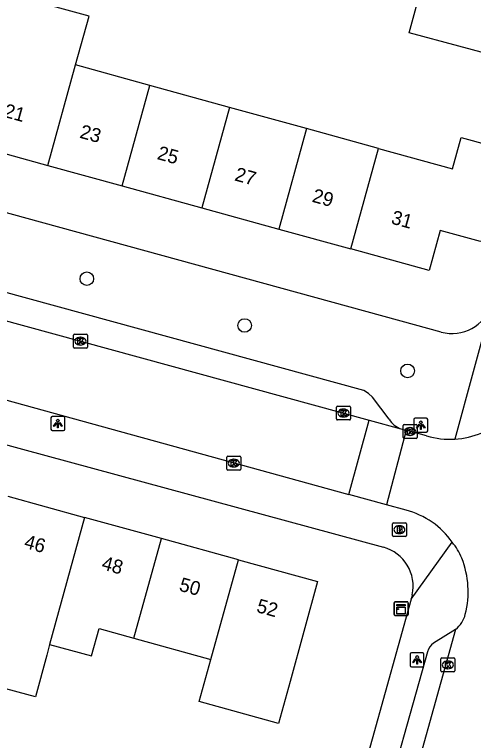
# Model space of a CAD drawing. Extents: x 159822 to 160765, y 380693 to 381634.
# Drawn here: x 160334.7 to 160367.7, y 380978.1 to 381030.3 of the extents above; entities that cross this region are included whole.
import ezdxf

# ---------------------------------------------------------------- set-up
doc = ezdxf.new("R2010")
doc.units = 0
for name, color, linetype in [('IMGEO_Boom', 7, 'Continuous'), ('IMGEO_Brandkraan', 7, 'Continuous'), ('IMGEO_Kast', 7, 'Continuous'), ('IMGEO_Kolk', 7, 'Continuous'), ('IMGEO_Lichtpunt', 7, 'Continuous'), ('IMGEO_Pand', 7, 'Continuous'), ('IMGEO_Pand_nummerreeks', 7, 'Continuous'), ('IMGEO_Rijbaan_lokaal_open', 7, 'Continuous'), ('IMGEO_Voetpad_open', 7, 'Continuous')]:
    doc.layers.add(name, color=color, linetype=linetype)

msp = doc.modelspace()

# ---------------------------------------------------------------- linework, layer by layer
at = {"layer": 'IMGEO_Boom'}
for centre in [(160339.893, 381011.267), (160351.236, 381007.905), (160362.95, 381004.636)]:
    msp.add_circle(centre, 0.489, dxfattribs=at)
at = {"layer": 'IMGEO_Brandkraan'}
for p, q in [((160361.861, 380992.794), (160361.861, 380993.646)), ((160361.936, 380993.72), (160362.788, 380993.72)), ((160362.349, 380993.5), (160362.374, 380993.5)), ((160362.862, 380993.646), (160362.862, 380992.794)), ((160362.372, 380992.94), (160362.347, 380992.94)), ((160362.788, 380992.72), (160361.936, 380992.72))]:
    msp.add_line(p, q, dxfattribs=at)
for points in [[(160361.861, 380992.794), (160361.861, 380993.646)], [(160361.936, 380993.72), (160362.788, 380993.72)], [(160362.862, 380993.646), (160362.862, 380992.794)], [(160362.209, 380993.42), (160362.209, 380993.02), (160362.422, 380993.02)], [(160362.44, 380993.42), (160362.209, 380993.42)], [(160362.388, 380993.339), (160362.334, 380993.339), (160362.334, 380993.263)], [(160362.334, 380993.263), (160362.387, 380993.263)], [(160362.396, 380993.187), (160362.334, 380993.187), (160362.334, 380993.106)], [(160362.334, 380993.106), (160362.396, 380993.106)], [(160362.788, 380992.72), (160361.936, 380992.72)]]:
    msp.add_lwpolyline(points, dxfattribs=at)
for centre, radius, start, end in [((160361.938, 380993.644), 0.0765, 91.552, 178.448), ((160361.938, 380993.644), 0.0765, 91.552, 178.448), ((160362.786, 380993.644), 0.0765, 1.552, 88.448), ((160362.786, 380993.644), 0.0765, 1.552, 88.448), ((160362.389, 380993.301), 0.0379, 267.8285, 90.9355), ((160362.397, 380993.146), 0.0404, 269.8759, 90.5077), ((160362.428, 380993.271), 0.251, 268.6676, 293.5347), ((160362.444, 380993.275), 0.145, 59.4692, 91.5367), ((160362.469, 380993.322), 0.0922, 285.5137, 58.1501), ((160362.474, 380993.13), 0.105, 301.3115, 78.989), ((160361.938, 380992.796), 0.0765, 181.552, 268.448), ((160361.938, 380992.796), 0.0765, 181.552, 268.448), ((160362.786, 380992.796), 0.0765, 271.552, 358.448), ((160362.786, 380992.796), 0.0765, 271.552, 358.448)]:
    msp.add_arc(centre, radius, start, end, dxfattribs=at)
for centre, major_axis, ratio, start_param, end_param in [((160362.348, 380993.22), (-0.387, 0.002), 0.722429, 4.712389, 7.853982), ((160362.373, 380993.22), (-0.39, 0.002), 0.717154, 1.570796, 4.712389)]:
    msp.add_ellipse(centre, major_axis=major_axis, ratio=ratio, start_param=start_param, end_param=end_param, dxfattribs=at)
at = {"layer": 'IMGEO_Kast'}
for p, q in [((160361.985, 380987.116), (160361.985, 380987.957)), ((160361.985, 380987.957), (160361.985, 380987.116)), ((160362.06, 380988.041), (160362.901, 380988.041)), ((160362.901, 380988.041), (160362.06, 380988.041)), ((160362.985, 380987.966), (160362.985, 380987.125)), ((160362.985, 380987.125), (160362.985, 380987.966)), ((160362.91, 380987.041), (160362.069, 380987.041)), ((160362.069, 380987.041), (160362.91, 380987.041))]:
    msp.add_line(p, q, dxfattribs=at)
for points in [[(160362.18, 380987.831), (160362.78, 380987.831), (160362.78, 380987.746), (160362.18, 380987.746), (160362.18, 380987.831)], [(160362.18, 380987.656), (160362.78, 380987.656), (160362.78, 380987.167), (160362.18, 380987.167), (160362.18, 380987.656)]]:
    msp.add_lwpolyline(points, dxfattribs=at)
msp.add_circle((160362.264, 380987.505), 0.0377, dxfattribs=at)
for centre, start, end in [((160362.063, 380987.963), 92.4484, 184.2845), ((160362.063, 380987.963), 92.4484, 184.2845), ((160362.907, 380987.963), 2.4484, 94.2845), ((160362.907, 380987.963), 2.4484, 94.2845), ((160362.063, 380987.119), 182.4484, 274.2845), ((160362.063, 380987.119), 182.4484, 274.2845), ((160362.907, 380987.119), 272.4484, 4.2845), ((160362.907, 380987.119), 272.4484, 4.2845)]:
    msp.add_arc(centre, 0.0779, start, end, dxfattribs=at)
at = {"layer": 'IMGEO_Kolk'}
for p, q in [((160338.931, 381006.354), (160338.931, 381007.206)), ((160339.006, 381007.28), (160339.858, 381007.28)), ((160339.419, 381007.06), (160339.444, 381007.06)), ((160339.932, 381007.206), (160339.932, 381006.354)), ((160339.858, 381006.28), (160339.006, 381006.28)), ((160339.442, 381006.5), (160339.417, 381006.5)), ((160357.844, 381001.181), (160357.844, 381002.033)), ((160357.919, 381002.107), (160358.771, 381002.107)), ((160358.332, 381001.887), (160358.357, 381001.887)), ((160358.845, 381002.033), (160358.845, 381001.181)), ((160358.355, 381001.327), (160358.33, 381001.327)), ((160358.771, 381001.107), (160357.919, 381001.107)), ((160362.704, 381000.782), (160363.556, 381000.782)), ((160362.629, 380999.856), (160362.629, 381000.708)), ((160363.117, 381000.562), (160363.142, 381000.562)), ((160363.63, 381000.708), (160363.63, 380999.856)), ((160363.556, 380999.782), (160362.704, 380999.782)), ((160363.14, 381000.002), (160363.115, 381000.002)), ((160349.955, 380997.581), (160349.955, 380998.433)), ((160350.03, 380998.507), (160350.882, 380998.507)), ((160350.443, 380998.287), (160350.468, 380998.287)), ((160350.956, 380998.433), (160350.956, 380997.581)), ((160350.466, 380997.727), (160350.441, 380997.727)), ((160350.882, 380997.507), (160350.03, 380997.507)), ((160365.343, 380983.068), (160365.343, 380983.92)), ((160365.418, 380983.994), (160366.27, 380983.994)), ((160365.831, 380983.774), (160365.856, 380983.774)), ((160366.344, 380983.92), (160366.344, 380983.068)), ((160365.854, 380983.214), (160365.829, 380983.214)), ((160366.27, 380982.994), (160365.418, 380982.994))]:
    msp.add_line(p, q, dxfattribs=at)
for points in [[(160338.931, 381006.354), (160338.931, 381007.206)], [(160339.006, 381007.28), (160339.858, 381007.28)], [(160339.932, 381007.206), (160339.932, 381006.354)], [(160339.252, 381006.98), (160339.375, 381006.98), (160339.375, 381006.829), (160339.505, 381006.98), (160339.669, 381006.98), (160339.523, 381006.829), (160339.676, 381006.58), (160339.524, 381006.58), (160339.439, 381006.744), (160339.375, 381006.677), (160339.375, 381006.58), (160339.252, 381006.58), (160339.252, 381006.98)], [(160339.858, 381006.28), (160339.006, 381006.28)], [(160357.844, 381001.181), (160357.844, 381002.033)], [(160357.919, 381002.107), (160358.771, 381002.107)], [(160358.845, 381002.033), (160358.845, 381001.181)], [(160358.165, 381001.807), (160358.288, 381001.807), (160358.288, 381001.656), (160358.418, 381001.807), (160358.582, 381001.807), (160358.436, 381001.656), (160358.589, 381001.407), (160358.437, 381001.407), (160358.352, 381001.571), (160358.288, 381001.504), (160358.288, 381001.407), (160358.165, 381001.407), (160358.165, 381001.807)], [(160358.771, 381001.107), (160357.919, 381001.107)], [(160362.704, 381000.782), (160363.556, 381000.782)], [(160362.629, 380999.856), (160362.629, 381000.708)], [(160362.95, 381000.482), (160363.073, 381000.482), (160363.073, 381000.331), (160363.203, 381000.482), (160363.367, 381000.482), (160363.221, 381000.331), (160363.374, 381000.082), (160363.222, 381000.082), (160363.137, 381000.246), (160363.073, 381000.179), (160363.073, 381000.082), (160362.95, 381000.082), (160362.95, 381000.482)], [(160363.63, 381000.708), (160363.63, 380999.856)], [(160363.556, 380999.782), (160362.704, 380999.782)], [(160349.955, 380997.581), (160349.955, 380998.433)], [(160350.03, 380998.507), (160350.882, 380998.507)], [(160350.276, 380998.207), (160350.399, 380998.207), (160350.399, 380998.056), (160350.529, 380998.207), (160350.693, 380998.207), (160350.547, 380998.056), (160350.7, 380997.807), (160350.548, 380997.807), (160350.463, 380997.971), (160350.399, 380997.904), (160350.399, 380997.807), (160350.276, 380997.807), (160350.276, 380998.207)], [(160350.956, 380998.433), (160350.956, 380997.581)], [(160350.882, 380997.507), (160350.03, 380997.507)], [(160365.343, 380983.068), (160365.343, 380983.92)], [(160365.418, 380983.994), (160366.27, 380983.994)], [(160365.664, 380983.694), (160365.787, 380983.694), (160365.787, 380983.543), (160365.917, 380983.694), (160366.081, 380983.694), (160365.935, 380983.543), (160366.088, 380983.294), (160365.936, 380983.294), (160365.851, 380983.458), (160365.787, 380983.391), (160365.787, 380983.294), (160365.664, 380983.294), (160365.664, 380983.694)], [(160366.344, 380983.92), (160366.344, 380983.068)], [(160366.27, 380982.994), (160365.418, 380982.994)]]:
    msp.add_lwpolyline(points, dxfattribs=at)
for centre, start, end in [((160339.008, 381007.204), 91.552, 178.448), ((160339.008, 381007.204), 91.552, 178.448), ((160339.856, 381007.204), 1.552, 88.448), ((160339.856, 381007.204), 1.552, 88.448), ((160339.008, 381006.356), 181.552, 268.448), ((160339.008, 381006.356), 181.552, 268.448), ((160339.856, 381006.356), 271.552, 358.448), ((160339.856, 381006.356), 271.552, 358.448), ((160357.921, 381002.031), 91.552, 178.448), ((160357.921, 381002.031), 91.552, 178.448), ((160358.769, 381002.031), 1.552, 88.448), ((160358.769, 381002.031), 1.552, 88.448), ((160357.921, 381001.183), 181.552, 268.448), ((160357.921, 381001.183), 181.552, 268.448), ((160358.769, 381001.183), 271.552, 358.448), ((160358.769, 381001.183), 271.552, 358.448), ((160362.706, 381000.706), 91.552, 178.448), ((160362.706, 381000.706), 91.552, 178.448), ((160363.554, 381000.706), 1.552, 88.448), ((160363.554, 381000.706), 1.552, 88.448), ((160362.706, 380999.858), 181.552, 268.448), ((160362.706, 380999.858), 181.552, 268.448), ((160363.554, 380999.858), 271.552, 358.448), ((160363.554, 380999.858), 271.552, 358.448), ((160350.032, 380998.431), 91.552, 178.448), ((160350.032, 380998.431), 91.552, 178.448), ((160350.88, 380998.431), 1.552, 88.448), ((160350.88, 380998.431), 1.552, 88.448), ((160350.032, 380997.583), 181.552, 268.448), ((160350.032, 380997.583), 181.552, 268.448), ((160350.88, 380997.583), 271.552, 358.448), ((160350.88, 380997.583), 271.552, 358.448), ((160365.42, 380983.918), 91.552, 178.448), ((160365.42, 380983.918), 91.552, 178.448), ((160366.268, 380983.918), 1.552, 88.448), ((160366.268, 380983.918), 1.552, 88.448), ((160365.42, 380983.07), 181.552, 268.448), ((160365.42, 380983.07), 181.552, 268.448), ((160366.268, 380983.07), 271.552, 358.448), ((160366.268, 380983.07), 271.552, 358.448)]:
    msp.add_arc(centre, 0.0765, start, end, dxfattribs=at)
for centre, major_axis, ratio, start_param, end_param in [((160339.418, 381006.78), (-0.387, 0.002), 0.722429, 4.712389, 7.853982), ((160339.443, 381006.78), (-0.39, 0.002), 0.717154, 1.570796, 4.712389), ((160358.331, 381001.607), (-0.387, 0.002), 0.722429, 4.712389, 7.853982), ((160358.356, 381001.607), (-0.39, 0.002), 0.717154, 1.570796, 4.712389), ((160363.116, 381000.282), (-0.387, 0.002), 0.722429, 4.712389, 7.853982), ((160363.141, 381000.282), (-0.39, 0.002), 0.717154, 1.570796, 4.712389), ((160350.442, 380998.007), (-0.387, 0.002), 0.722429, 4.712389, 7.853982), ((160350.467, 380998.007), (-0.39, 0.002), 0.717154, 1.570796, 4.712389), ((160365.83, 380983.494), (-0.387, 0.002), 0.722429, 4.712389, 7.853982), ((160365.855, 380983.494), (-0.39, 0.002), 0.717154, 1.570796, 4.712389)]:
    msp.add_ellipse(centre, major_axis=major_axis, ratio=ratio, start_param=start_param, end_param=end_param, dxfattribs=at)
at = {"layer": 'IMGEO_Lichtpunt'}
for p, q in [((160338.217, 381001.355), (160337.409, 381001.355)), ((160338.217, 381001.355), (160337.409, 381001.355)), ((160337.315, 381001.26), (160337.315, 381000.453)), ((160337.315, 381001.26), (160337.315, 381000.453)), ((160338.311, 381000.453), (160338.311, 381001.26)), ((160338.311, 381000.453), (160338.311, 381001.26)), ((160363.398, 381001.141), (160363.398, 381000.334)), ((160363.398, 381001.141), (160363.398, 381000.334)), ((160364.3, 381001.236), (160363.492, 381001.236)), ((160364.3, 381001.236), (160363.492, 381001.236)), ((160364.394, 381000.334), (160364.394, 381001.141)), ((160364.394, 381000.334), (160364.394, 381001.141)), ((160337.409, 381000.359), (160338.217, 381000.359)), ((160337.409, 381000.359), (160338.217, 381000.359)), ((160363.492, 381000.24), (160364.3, 381000.24)), ((160363.492, 381000.24), (160364.3, 381000.24)), ((160363.132, 380984.261), (160363.132, 380983.454)), ((160363.132, 380984.261), (160363.132, 380983.454)), ((160364.034, 380984.356), (160363.226, 380984.356)), ((160364.034, 380984.356), (160363.226, 380984.356)), ((160364.128, 380983.454), (160364.128, 380984.261)), ((160364.128, 380983.454), (160364.128, 380984.261)), ((160363.226, 380983.36), (160364.034, 380983.36)), ((160363.226, 380983.36), (160364.034, 380983.36))]:
    msp.add_line(p, q, dxfattribs=at)
for points in [[(160337.689, 381000.924), (160337.728, 381000.896), (160337.54, 381000.634), (160337.502, 381000.661), (160337.689, 381000.924)], [(160337.791, 381000.876), (160337.838, 381000.876), (160337.838, 381000.554), (160337.791, 381000.554), (160337.791, 381000.876)], [(160337.901, 381000.896), (160337.939, 381000.923), (160338.126, 381000.661), (160338.087, 381000.633), (160337.901, 381000.896)], [(160363.772, 381000.805), (160363.811, 381000.777), (160363.623, 381000.515), (160363.585, 381000.542), (160363.772, 381000.805)], [(160363.984, 381000.777), (160364.022, 381000.804), (160364.209, 381000.542), (160364.17, 381000.514), (160363.984, 381000.777)], [(160363.874, 381000.757), (160363.921, 381000.757), (160363.921, 381000.435), (160363.874, 381000.435), (160363.874, 381000.757)], [(160363.506, 380983.925), (160363.545, 380983.897), (160363.357, 380983.635), (160363.319, 380983.662), (160363.506, 380983.925)], [(160363.608, 380983.877), (160363.655, 380983.877), (160363.655, 380983.555), (160363.608, 380983.555), (160363.608, 380983.877)], [(160363.718, 380983.897), (160363.756, 380983.924), (160363.943, 380983.662), (160363.904, 380983.634), (160363.718, 380983.897)]]:
    msp.add_lwpolyline(points, dxfattribs=at)
for centre in [(160337.814, 381001.058), (160363.897, 381000.939), (160363.631, 380984.059)]:
    msp.add_circle(centre, 0.0994, dxfattribs=at)
for centre, start, end in [((160337.409, 381001.26), 90, 180), ((160337.409, 381001.26), 90, 180), ((160338.217, 381001.26), 0, 90), ((160338.217, 381001.26), 0, 90), ((160363.492, 381001.141), 90, 180), ((160363.492, 381001.141), 90, 180), ((160364.3, 381001.141), 0, 90), ((160364.3, 381001.141), 0, 90), ((160337.409, 381000.453), 180, 270), ((160337.409, 381000.453), 180, 270), ((160338.217, 381000.453), 270, 0), ((160338.217, 381000.453), 270, 360), ((160363.492, 381000.334), 180, 270), ((160363.492, 381000.334), 180, 270), ((160364.3, 381000.334), 270, 0), ((160364.3, 381000.334), 270, 360), ((160363.226, 380984.261), 90, 180), ((160363.226, 380984.261), 90, 180), ((160364.034, 380984.261), 0, 90), ((160364.034, 380984.261), 0, 90), ((160363.226, 380983.454), 180, 270), ((160363.226, 380983.454), 180, 270), ((160364.034, 380983.454), 270, 0), ((160364.034, 380983.454), 270, 360)]:
    msp.add_arc(centre, 0.0946, start, end, dxfattribs=at)
at = {"layer": 'IMGEO_Pand'}
for points in [[(160371.389, 381031.436), (160370.202, 381027.038), (160363.071, 381028.962), (160364.258, 381033.36)], [(160339.087, 381026.638), (160340.057, 381030.161), (160334.618, 381031.659), (160334.524, 381031.318)], [(160337.097, 381019.414), (160339.087, 381026.638)], [(160344.429, 381025.165), (160339.087, 381026.638)], [(160342.439, 381017.942), (160344.429, 381025.165)], [(160350.154, 381023.587), (160344.429, 381025.165)], [(160350.154, 381023.587), (160348.164, 381016.364)], [(160355.687, 381022.062), (160350.154, 381023.587)], [(160355.687, 381022.062), (160353.697, 381014.839)], [(160360.863, 381020.636), (160355.687, 381022.062)], [(160360.863, 381020.636), (160366.179, 381019.17), (160366.803, 381021.433), (160371.094, 381020.247), (160369.549, 381014.715), (160368.199, 381013.94), (160365.302, 381014.74), (160364.508, 381011.859), (160358.872, 381013.412)], [(160331.657, 381020.914), (160337.097, 381019.414)], [(160358.872, 381013.412), (160360.863, 381020.636)], [(160337.097, 381019.414), (160342.439, 381017.942)], [(160342.439, 381017.942), (160348.164, 381016.364)], [(160348.164, 381016.364), (160353.697, 381014.839)], [(160353.697, 381014.839), (160358.872, 381013.412)], [(160334.207, 380995.633), (160339.735, 380994.106)], [(160339.735, 380994.106), (160337.211, 380984.969)], [(160345.263, 380992.58), (160339.735, 380994.106)], [(160343.282, 380985.409), (160345.263, 380992.58)], [(160350.789, 380991.053), (160345.263, 380992.58)], [(160350.789, 380991.053), (160356.485, 380989.48), (160354.501, 380982.306), (160353.665, 380979.283), (160347.973, 380980.857), (160348.81, 380983.88)], [(160348.81, 380983.88), (160350.789, 380991.053)], [(160337.211, 380984.969), (160337.014, 380984.2), (160336.213, 380981.202), (160330.658, 380982.686), (160331.459, 380985.684)], [(160337.211, 380984.969), (160340.232, 380984.135), (160340.776, 380986.102), (160343.282, 380985.409)], [(160343.282, 380985.409), (160348.81, 380983.88)]]:
    msp.add_lwpolyline(points, dxfattribs=at)
at = {"layer": 'IMGEO_Rijbaan_lokaal_open'}
for points in [[(160314.835, 381013.509), (160360.19, 381001.089)], [(160313.429, 381008.229), (160358.736, 380995.757)], [(160358.736, 380995.757), (160360.19, 381001.089)], [(160360.19, 381001.089), (160362.476, 381000.483)], [(160362.844, 381000.385), (160361.434, 380994.997)], [(160362.476, 381000.483), (160362.844, 381000.385)], [(160364.317, 380999.966), (160362.844, 381000.385)], [(160361.434, 380994.997), (160358.736, 380995.757)], [(160362.838, 380994.62), (160361.434, 380994.997)], [(160366.401, 380986.044), (160362.306, 380971.33)]]:
    msp.add_lwpolyline(points, dxfattribs=at)
for centre, radius, start, end in [((160365.995, 381005.479), 5.763, 253.074, 273.4834), ((160365.994, 381005.47), 5.753, 273.4984, 293.4886), ((160361.394, 380989.014), 5.789, 54.9814, 75.5574), ((160361.407, 380989.022), 5.775, 34.7632, 55.0375), ((160363.385, 380989.861), 3.697, 20.6981, 41.5814), ((160360.781, 380988.762), 6.523, 345.5964, 21.6466), ((160365.131, 380987.624), 2.027, 308.8028, 346.1668)]:
    msp.add_arc(centre, radius, start, end, dxfattribs=at)
at = {"layer": 'IMGEO_Voetpad_open'}
for points in [[(160365.368, 381007.43), (160363.438, 381007.96), (160307.725, 381023.254), (160306.239, 381023.664)], [(160361.63, 381001.162), (160360.42, 381002.756), (160360.135, 381003.011), (160359.806, 381003.238), (160307.446, 381017.566)], [(160368.984, 381009.402), (160366.345, 380999.727)], [(160312.885, 381005.214), (160331.627, 381000), (160361.208, 380991.958)], [(160363.205, 380988.215), (160366.151, 380992.315)], [(160363.29, 380988.528), (160363.205, 380988.215)], [(160363.205, 380988.215), (160356.667, 380964.739)], [(160366.401, 380986.044), (160364.812, 380985.064)], [(160364.374, 380984.439), (160360.816, 380971.732)]]:
    msp.add_lwpolyline(points, dxfattribs=at)
for centre, radius, start, end in [((160366.132, 381010.33), 2.999, 255.2354, 341.9767), ((160362.898, 381001.875), 1.455, 209.3632, 253.1357), ((160360.429, 380989.139), 2.925, 347.9524, 74.5628), ((160365.493, 380984.121), 1.164, 125.8333, 164.1212)]:
    msp.add_arc(centre, radius, start, end, dxfattribs=at)

# ---------------------------------------------------------------- texts
at = {"layer": 'IMGEO_Pand_nummerreeks'}
for s, rotation, p in [('21', 344.5906, (160333.859, 381022.921)), ('23', 344.5906, (160339.319, 381021.416)), ('25', 344.5906, (160344.888, 381019.881)), ('27', 344.5906, (160350.458, 381018.346)), ('29', 344.5906, (160356.027, 381016.811)), ('31', 344.5906, (160361.705, 381015.246)), ('46', 344.5588, (160335.324, 380991.923)), ('48', 344.5596, (160340.895, 380990.383)), ('50', 344.5596, (160346.464, 380988.845)), ('52', 344.5596, (160352.027, 380987.309))]:
    msp.add_text(s, height=1, rotation=rotation, dxfattribs=at).set_placement(p)

doc.saveas('drawing.dxf')
